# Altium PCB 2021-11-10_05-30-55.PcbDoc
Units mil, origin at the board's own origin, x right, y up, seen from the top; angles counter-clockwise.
Board outline 2000 x 2000 mil, 4 copper layers (Top Layer, MidLayer1, MidLayer2, Bottom Layer); 17 components, 9 nets, 38 pads, 30 vias.
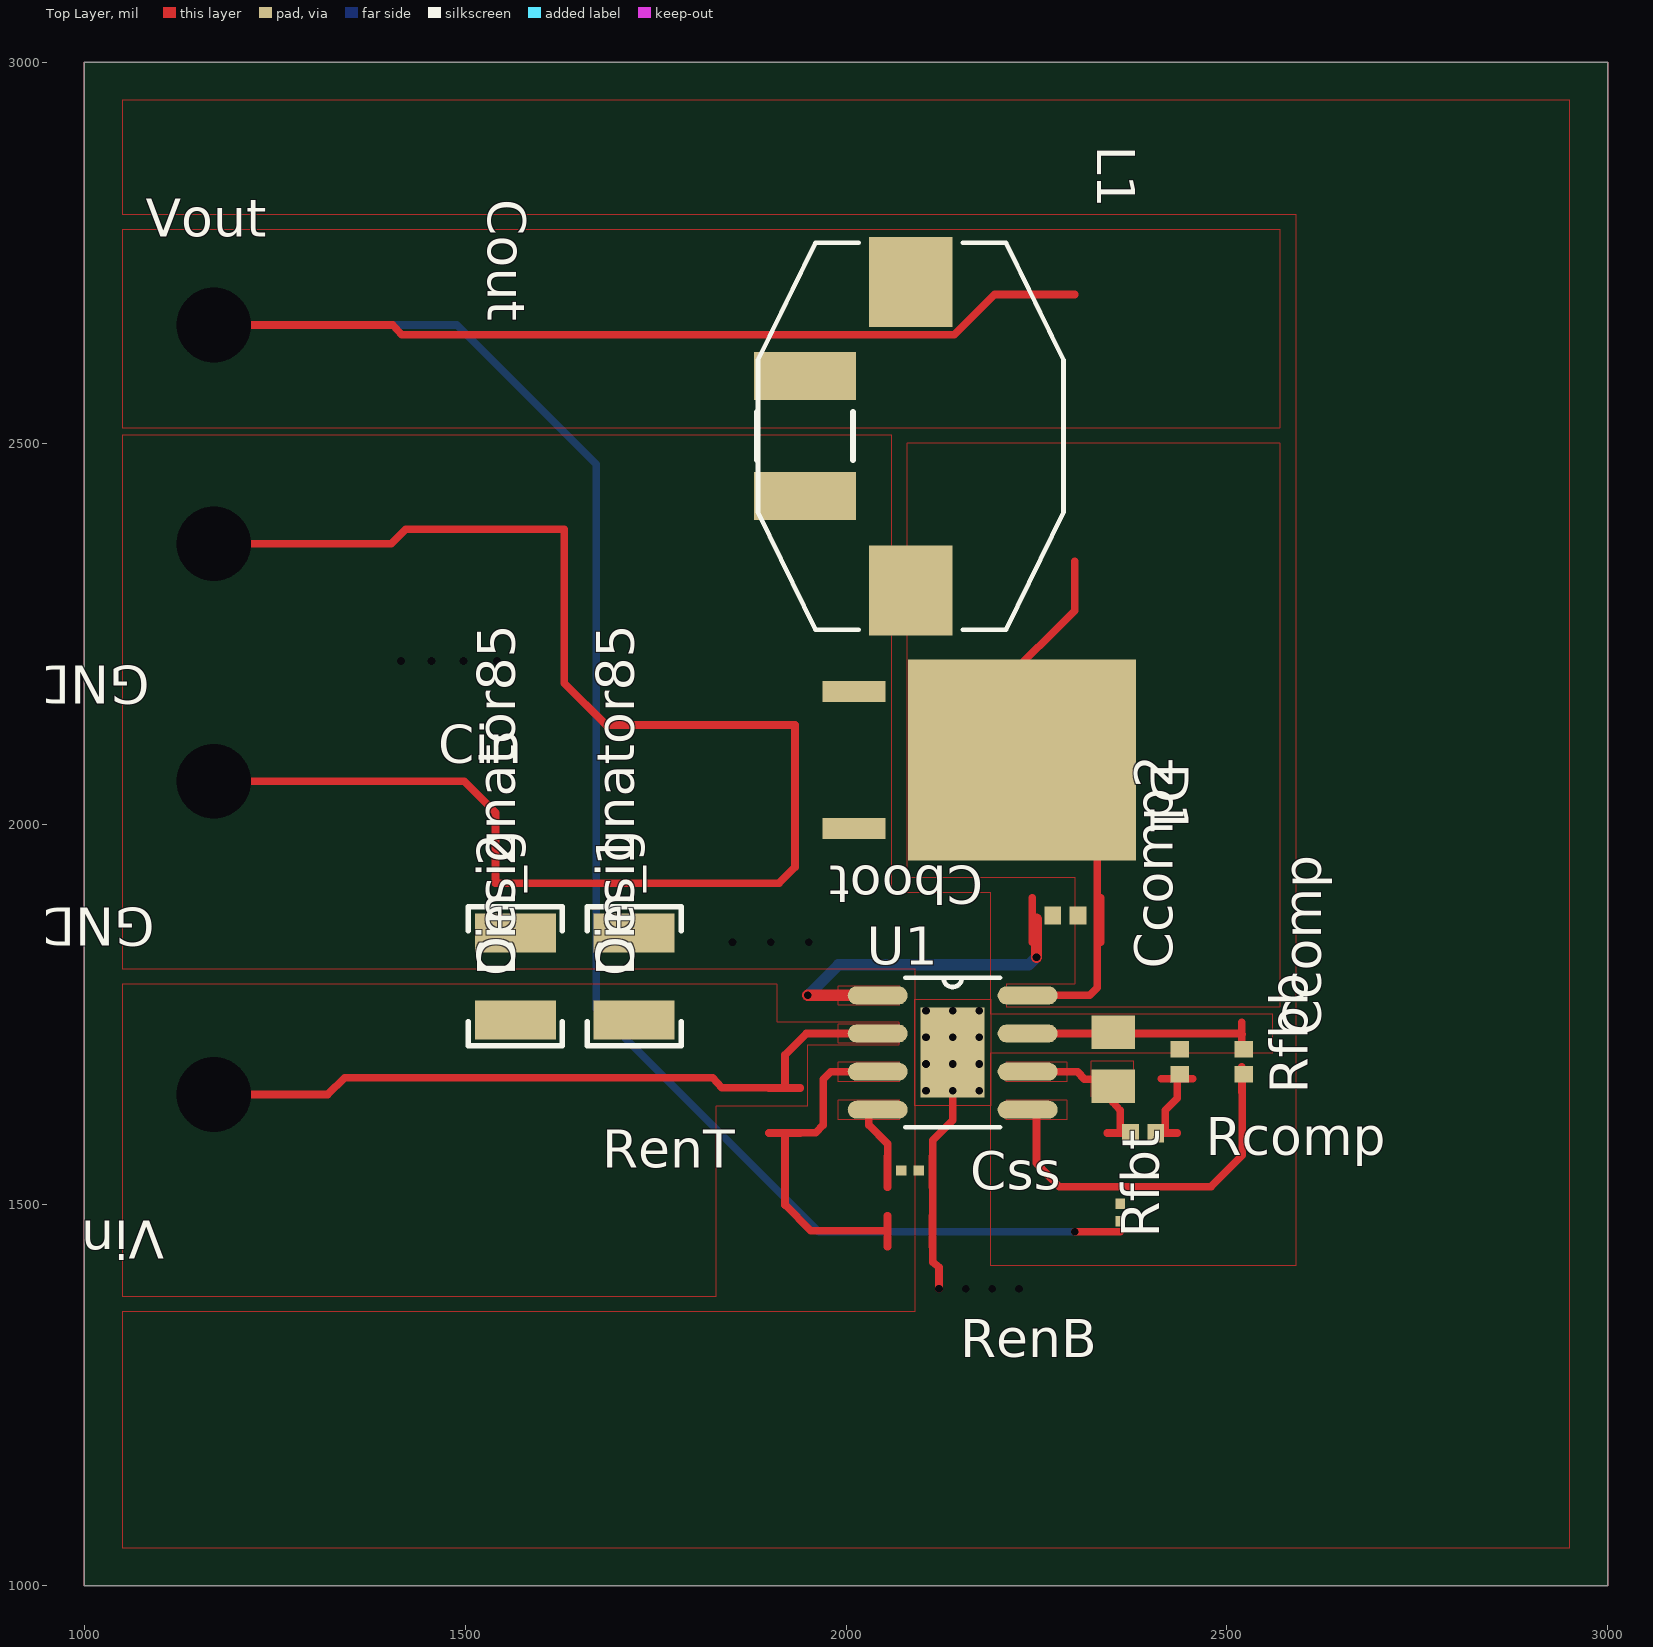
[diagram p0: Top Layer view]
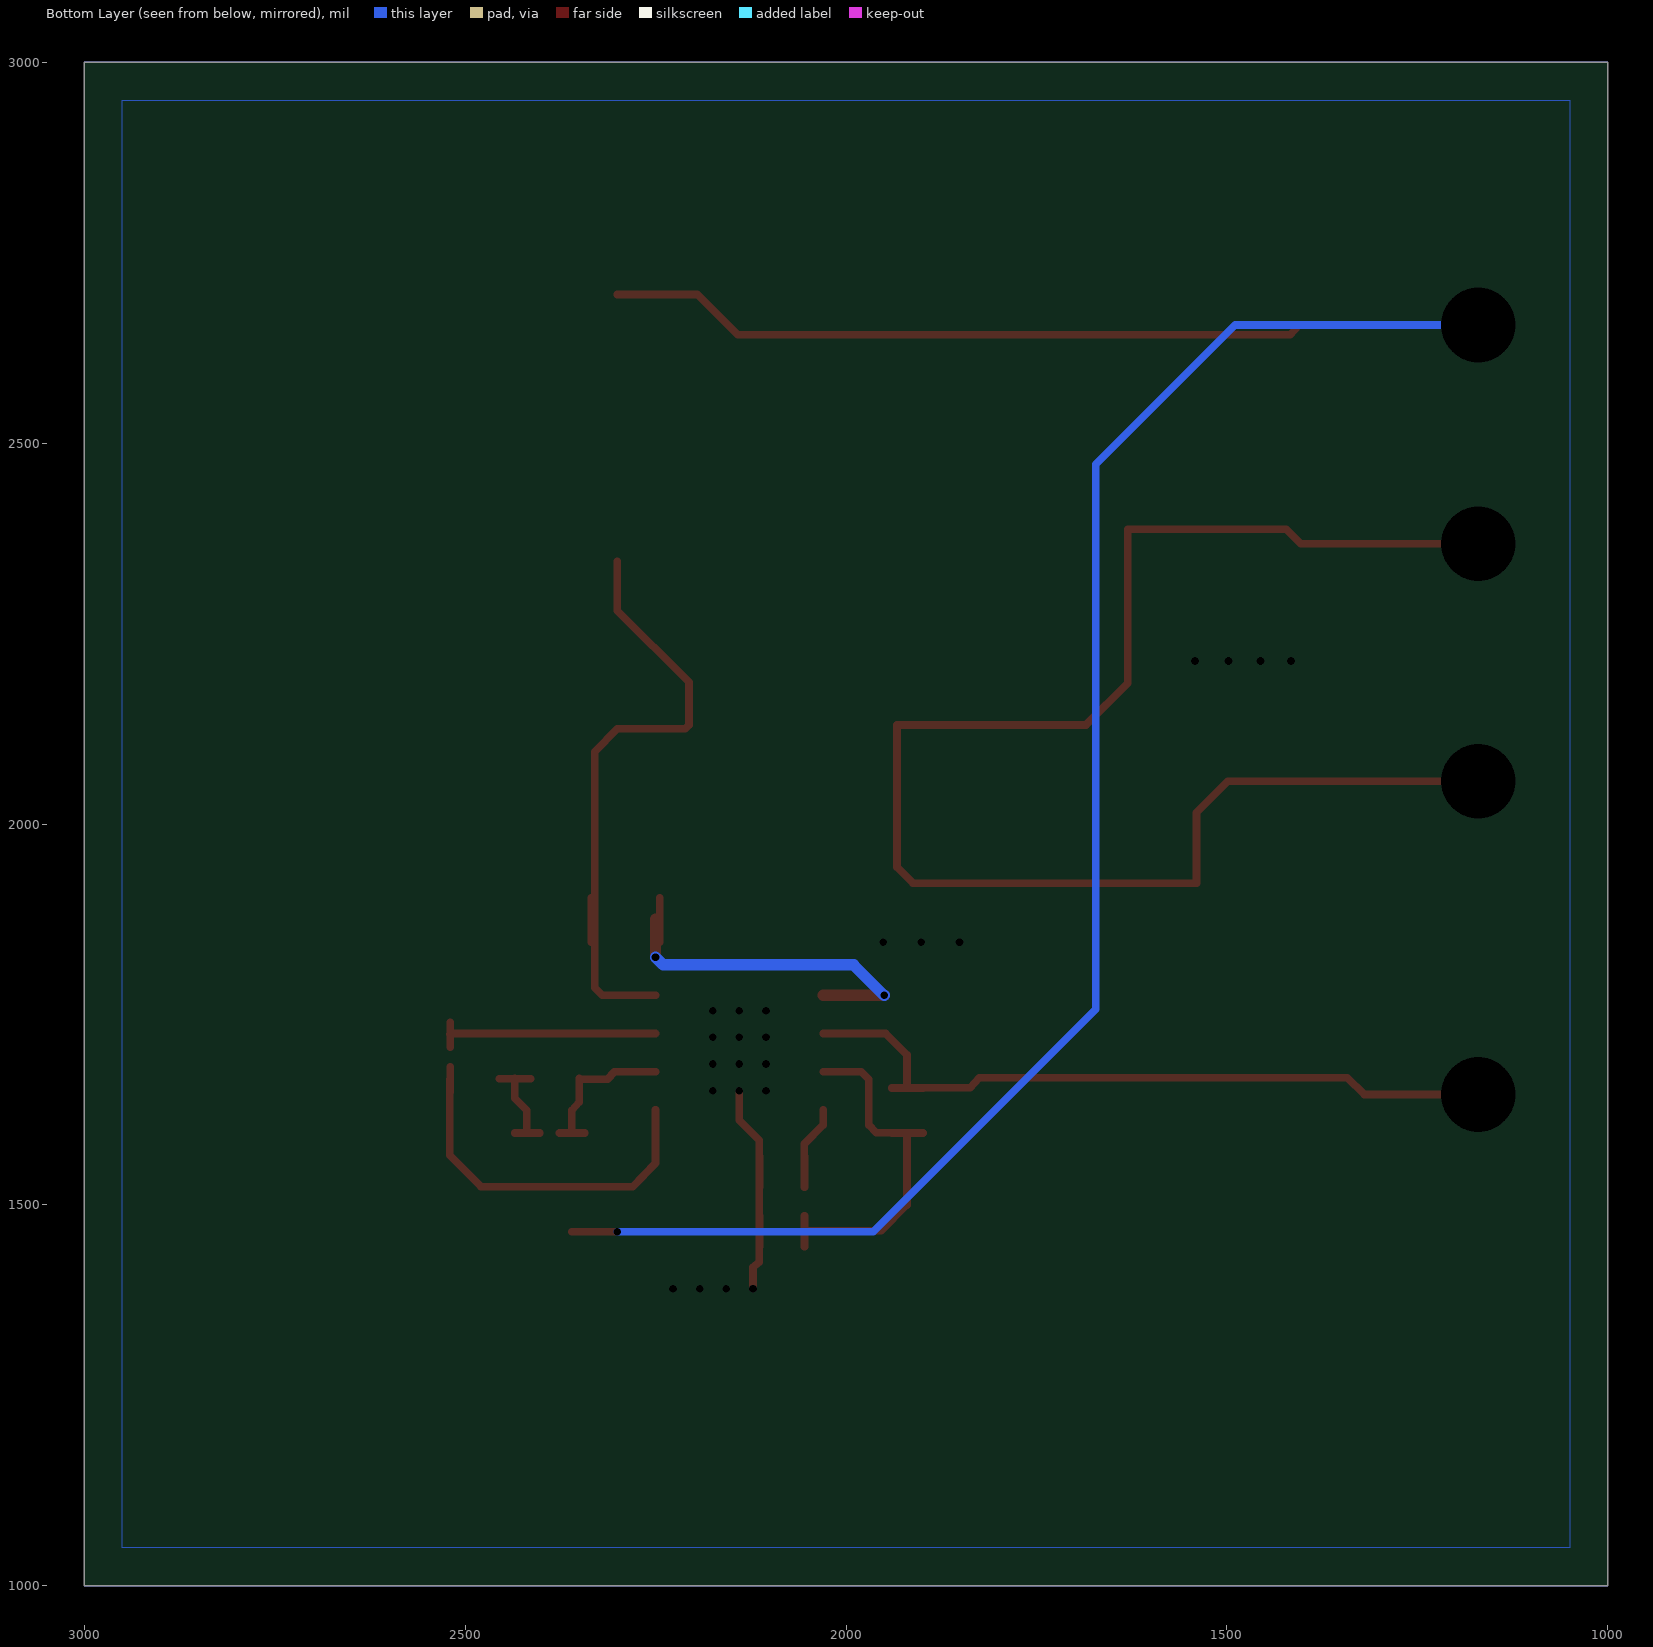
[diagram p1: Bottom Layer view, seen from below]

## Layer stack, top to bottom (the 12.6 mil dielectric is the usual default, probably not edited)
Top Layer: signal copper 1.4
Dielectric: core 12.6, FR-4, Dk 4.8
MidLayer1: signal copper 1.4
Dielectric: prepreg 12.6, FR-4, Dk 4.8
MidLayer2: signal copper 1.4
Dielectric: core 12.6, FR-4, Dk 4.8
Bottom Layer: signal copper 1.4

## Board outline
1000,1000 3000,1000 3000,3000 1000,3000

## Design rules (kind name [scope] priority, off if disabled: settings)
PlaneConnect [All] p0: scope1count=1 scope1_0_kind=Board scope1_0_value=Board scope2count=1 scope2_0_kind=Board scope2_0_value=Board commentlength=0 planeconnectstyle=Direct reliefexpansion=20 reliefentries=4 reliefconductorwidth=10 reliefairgap=10
PlaneConnect [All] p1: planeconnectstyle=Direct reliefexpansion=20 reliefentries=4 reliefconductorwidth=10 reliefairgap=10
PolygonConnect [All] p0: scope1count=1 scope1_0_kind=Board scope1_0_value=Board scope2count=1 scope2_0_kind=Board scope2_0_value=Board commentlength=0 connectstyle=Direct reliefconductorwidth=10 reliefentries=4 polygonreliefangle="90 Angle"
PolygonConnect [All] p1: connectstyle=Direct reliefconductorwidth=10 reliefentries=4 polygonreliefangle="90 Angle"

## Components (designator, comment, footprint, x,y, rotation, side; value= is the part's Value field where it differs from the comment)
Cboot "" 0402 2288,1880 r180 top
Ccomp "" 0402 2438,1688 r90 top
Ccomp2 "" 0805 2351,1691 r90 top
Cin_1 "" 1210 1722,1800 r90 top
Cin_2 "" 1210 1566,1800 r90 top
Cout "" 1812_320 1946,2509 r270 top
Css "" 0201 2084,1545 r0 top
D1 "" DPAK 2225,2084 r270 top
GND "" TP-1502 1168,2055 r180 top
GND1 "" TP-1502 1168,2367 r180 top
L1 "" SDR1005 2085,2509 r270 top
Rcomp "" 0402 2390,1594 r0 top
Rfbb "" 0402 2522,1688 r90 top
Rfbt "" 0201 2360,1490 r90 top
U1 "" DDA0008H 2140,1700 r0 top
Vin "" TP-1502 1168,1644 r180 top
Vout "" TP-1502 1168,2655 r0 top

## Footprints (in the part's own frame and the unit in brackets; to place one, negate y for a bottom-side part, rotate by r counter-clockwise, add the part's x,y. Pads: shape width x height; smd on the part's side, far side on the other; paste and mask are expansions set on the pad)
0201 [mil]
  rect 14x13 smd: 1(-11.5,0) 2(11.5,0)
0402 [mil]
  rect 22x24 smd: 1(-16.5,0) 2(16.5,0)
0805 [mil]
  rect 44x57 smd: 1(-35.5,0) 2(35.5,0)
1210 [mm]
  rect 1.3x2.7 smd: 1(-1.45,0) 2(1.45,0)
  silkscreen extent -2.32,-1.57 2.32,1.57
1812_320 [mm]
  rect 1.6x3.4 smd: 1(-2,0) 2(2,0)
  silkscreen extent -0.8,-1.6 0.8,1.6
DDA0008H [mm]
  oval 2x0.6 smd: 1(-2.5,1.905) 2(-2.5,0.635) 3(-2.5,-0.635) 4(-2.5,-1.905) 5(2.5,-1.905) 6(2.5,-0.635) 7(2.5,0.635) 8(2.5,1.905)
  rect 2.13x3 smd: 9(0,0)
  silkscreen extent -1.58,-2.49 1.58,2.49
DPAK [mm]
  rect 0.701x2.111 smd: 1(-2.28,-5.45) 3(2.28,-5.45)
  rect 6.7x7.605 smd: 2(0,0.152)
SDR1005 [mil]
  rect 118x110 smd: 1(-202.5,0) 2(202.5,0)
  silkscreen extent -254,-201 254,201
TP-1502 [mil]
  round 65 hole 32: 1(0,0)

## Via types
v1: diameter 0, hole 10, Top Layer to Bottom Layer, 26 vias
v2: diameter 0, hole 98, Top Layer to Bottom Layer, 4 vias

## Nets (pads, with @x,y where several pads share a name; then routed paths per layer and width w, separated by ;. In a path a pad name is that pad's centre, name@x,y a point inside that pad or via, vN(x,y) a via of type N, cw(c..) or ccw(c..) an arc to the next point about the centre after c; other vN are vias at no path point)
0: Ccomp2.2 Ccomp.2 Cin_1.2 Cin_2.2 Cout.2 Css.2 D1.1 D1.3 GND1.1 GND.1 Rfbb.2 U1.7 U1.9 | length 2765.1
  Top Layer w10: v2(1170,2056) 1499,2056 1540,2015 1540,1922 1912,1922 1933,1943 1933,2130 1685,2130 1630,2185 1630,2387 1422,2387 1403,2368 v2(1170,2368) ; 2113.5,1445 2113.5,1486 ; 2113.5,1523 2113.5,1564 ; v1(2122,1390) 2122,1418 2114,1425 2114,1466 2114,1544 2114,1585 2140,1611 v1(2140,1650) ; U1.7@2250,1725 2519,1725 2520,1724 ; 2414,1724.5 2455,1724.5 ; Rfbb.2@2519.5,1707 2519.5,1740
  other v1: 2157,1390 2192,1390 2227,1390 2105,1650 2175,1650 2105,1685 2140,1685 2175,1685 2105,1720 2140,1720 2175,1720 2105,1755 2140,1755 2175,1755 1851,1845 1901,1845 1951,1845 1416,2214 1456,2214 1498,2214 1542,2214
1: Cboot.1 U1.1 | length 508.7
  Top Layer w10: 2244.5,1845 2244.5,1903
  Top Layer w15: v1(1950,1775) U1.1@2030,1775 ; v1(2250,1825) 2250,1875
  Bottom Layer w15: v1(1950,1775) 1990,1815 2240,1815 v1(2250,1825)
2: Cin_1.1 Cin_2.1 U1.2 Vin.1 | length 970.4
  Top Layer w10: v2(1170,1645) 1320,1645 1342,1667 1540,1667 1825,1667 1837,1654 1920,1654 1920,1697 1948,1725 U1.2@2030,1725 ; 1899,1653.5 1940,1653.5
4: Ccomp2.1 Rcomp.1 U1.6 | length 212.3
  Top Layer w10: U1.6@2250,1675 2304,1675 2313,1665 Ccomp2.1@2350,1665 ; 2343,1594.5 Rcomp.1@2376,1594.5 ; Ccomp2.1@2350,1666 Ccomp2.1@2350,1665 ; 2360,1595 2360,1624 2350,1635 Ccomp2.1@2350,1665
5: Rfbb.1 Rfbt.2 U1.3 U1.5 | length 1007.5
  Top Layer w10: 1899,1594.5 1940,1594.5 ; U1.3@2030,1675 1980,1675 1970,1665 1970,1605 1960,1595 1920,1595 1920,1500 1954,1466 2055,1466 ; 2054.5,1445 2054.5,1486 ; U1.5@2250,1625 2250,1555 2280,1524 2360,1524 2479,1524 2520,1565 Rfbb.1@2520,1665 ; 2519.5,1648 Rfbb.1@2519.5,1681
6: Css.1 U1.4 | length 132.4
  Top Layer w10: U1.4@2030,1625 2030,1605 2055,1580 2055,1544 ; 2054.5,1523 2054.5,1564
7: Cboot.2 D1.2 L1.2 U1.8 | length 844.6
  Top Layer w10: U1.8@2250,1775 2320,1775 2330,1785 2330,1875 2330,2095 2300,2125 2211,2125 2206,2130 2206,2186 2300,2280 2300,2345 ; 2334.5,1845 2334.5,1903
8: Cout.1 L1.1 Rfbt.1 Vout.1 | length 3259.4
  Top Layer w10: v2(1170,2655) 1405,2655 1417,2642 1630,2642 2142,2642 2195,2695 2300,2695 ; v1(2300,1465) 2360,1465
  Bottom Layer w10: v2(1170,2655) 1489,2655 1672,2472 1672,1757 1964,1465 v1(2300,1465)
9: Ccomp.1 Rcomp.2 | length 151.6
  Top Layer w10: Rcomp.2@2402,1594.5 2435,1594.5 ; 2414,1665.5 2455,1665.5 ; 2419,1595 2419,1624 2435,1640 Ccomp.1@2435,1666

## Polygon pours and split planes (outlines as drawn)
4 on Top Layer " " (solid, pour order 0): 2322,1642 2322,1689 2377,1689 2377,1642
1 on Top Layer " " (solid, pour order 1): 1990,1762 1990,1788 2070,1788 2070,1762
2 on Top Layer " " (solid, pour order 2): 1990,1712 1990,1738 2070,1738 2070,1712
5 on Top Layer " " (solid, pour order 3): 1990,1662 1990,1688 2070,1688 2070,1662
6 on Top Layer " " (solid, pour order 4): 1990,1612 1990,1638 2070,1638 2070,1612
4 on Top Layer " " (solid, pour order 5): 2210,1662 2210,1688 2290,1688 2290,1662
5 on Top Layer " " (solid, pour order 6): 2210,1612 2210,1638 2290,1638 2290,1612
2 on Top Layer " " (solid, pour order 7): 1050,1380 1830,1380 1830,1630 1950,1630 1950,1710 2070,1710 2070,1740 1910,1740 1910,1790 1050,1790
8 on Top Layer " " (solid, pour order 8): 2570,2520 2570,2780 1050,2780 1050,2520
7 on Top Layer " " (solid, pour order 9): 2210,1760 2570,1760 2570,2500 2080,2500 2080,1930 2300,1930 2300,1790 2210,1790
0 on Top Layer " " (solid, pour order 10): 2090,1630 2090,1770 2190,1770 2190,1630
0 on Top Layer " " (solid, pour order 12): 2950,1050 2950,2950 1050,2950 1050,2800 2590,2800 2590,1420 2190,1420 2190,1700 2560,1700 2560,1750 2190,1750 2190,1910 2060,1910 2060,2510 1050,2510 1050,1810 2090,1810 2090,1360 1050,1360 1050,1050
0 on Bottom Layer " " (solid, pour order 11): 2950,1050 2950,2950 1050,2950 1050,1050

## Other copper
Multi-Layer:
  the board outline again, w1

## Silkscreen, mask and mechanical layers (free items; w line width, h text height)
Top Overlay:
  text "Cin" at 1465,2080 h50
  text "RenT" at 1680,1549 h50
  text "RenB" at 2150,1300 h50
